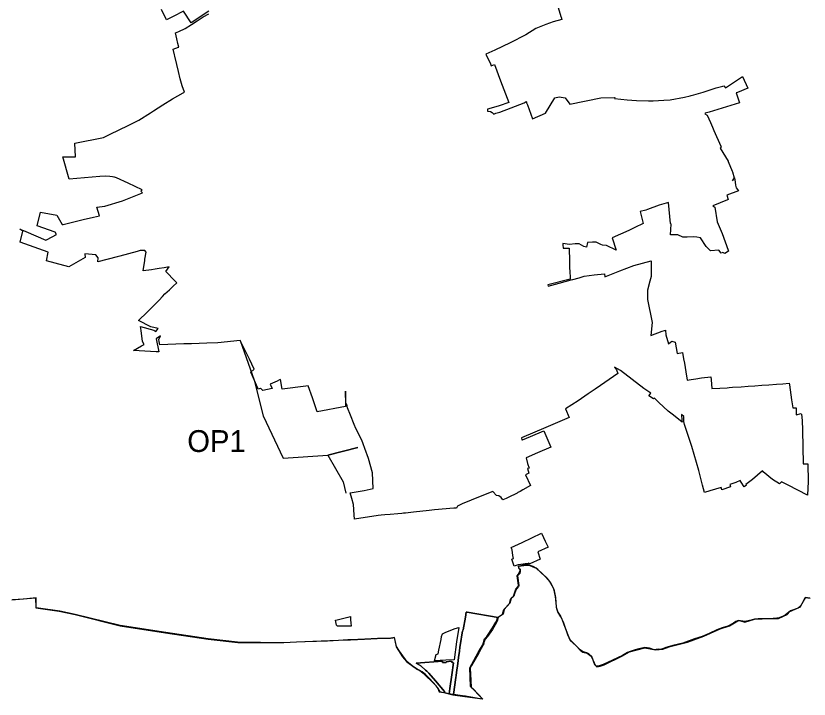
# Model space of a CAD drawing. Extents: x -478490 to -472450, y -1118050 to -1109550.
# Drawn here: x -477155 to -474975, y -1113498 to -1111620 of the extents above; entities that cross this region are included whole.
import ezdxf

# ---------------------------------------------------------------- set-up
doc = ezdxf.new("R2010")
doc.units = 0
for name, color, linetype in [('hranice kú', 7, 'Continuous'), ('Implicitní', 7, 'Continuous'), ('ObPÚ', 7, 'Continuous')]:
    doc.layers.add(name, color=color, linetype=linetype)

msp = doc.modelspace()

# ---------------------------------------------------------------- linework, layer by layer
at = {"layer": 'hranice kú'}
for p, q in [((-475773.3, -1113132.4), (-475752, -1113129.2)), ((-475772.9, -1113137.3), (-475773.3, -1113132.4)), ((-475770, -1113140.3), (-475772.9, -1113137.3)), ((-475752, -1113129.2), (-475745.4, -1113129.5)), ((-475745.4, -1113129.5), (-475736, -1113133)), ((-475736, -1113133), (-475725.4, -1113138.1)), ((-475725.4, -1113138.1), (-475700.6, -1113160.1)), ((-475777.5, -1113158.9), (-475773.1, -1113154.3)), ((-475773.7, -1113184.2), (-475777.5, -1113158.9)), ((-475773.1, -1113154.3), (-475768.7, -1113144)), ((-475768.7, -1113144), (-475770, -1113140.3)), ((-475700.6, -1113160.1), (-475690.7, -1113170.6)), ((-475690.7, -1113170.6), (-475685.4, -1113178)), ((-475685.4, -1113178), (-475676.7, -1113195.1)), ((-475787.5, -1113214.7), (-475780.7, -1113195.1)), ((-475780.7, -1113195.1), (-475774.1, -1113188)), ((-475774.1, -1113188), (-475773.7, -1113184.2)), ((-475676.7, -1113195.1), (-475671.9, -1113217.9)), ((-477165.8, -1113224.6), (-477134.7, -1113222.1)), ((-477134.7, -1113222.1), (-477100.4, -1113219)), ((-477100.4, -1113219), (-477099.3, -1113246.8)), ((-475798.5, -1113234.6), (-475794.6, -1113221.1)), ((-475794.6, -1113221.1), (-475787.5, -1113214.7)), ((-475671.9, -1113217.9), (-475669.7, -1113244.5)), ((-474998.9, -1113244.1), (-474985.7, -1113218)), ((-474985.7, -1113218), (-474972, -1113220.4)), ((-477099.3, -1113246.8), (-477035.2, -1113255.8)), ((-475814.3, -1113251.4), (-475798.5, -1113234.6)), ((-475669.7, -1113244.5), (-475665.3, -1113258.5)), ((-475027.8, -1113257.1), (-474998.9, -1113244.1)), ((-477035.2, -1113255.8), (-476991.4, -1113264.9)), ((-476991.4, -1113264.9), (-476867.7, -1113295.9)), ((-475831.5, -1113273.2), (-475817.6, -1113264.1)), ((-475817.6, -1113264.1), (-475814.3, -1113251.4)), ((-475665.3, -1113258.5), (-475658.2, -1113269.2)), ((-475658.2, -1113269.2), (-475650.2, -1113288)), ((-475059, -1113276.2), (-475035.7, -1113264.8)), ((-475035.7, -1113264.8), (-475027.8, -1113257.1)), ((-475844.9, -1113301.8), (-475835.7, -1113286.1)), ((-475835.7, -1113286.1), (-475833, -1113280.7)), ((-475833, -1113280.7), (-475831.5, -1113273.2)), ((-475650.2, -1113288), (-475638.7, -1113319.8)), ((-475193.7, -1113296.3), (-475171.4, -1113282.5)), ((-475171.4, -1113282.5), (-475166.6, -1113281.7)), ((-475166.6, -1113281.7), (-475151.7, -1113286)), ((-475151.7, -1113286), (-475125.2, -1113277.7)), ((-475125.2, -1113277.7), (-475104.3, -1113277.2)), ((-475104.3, -1113277.2), (-475059, -1113276.2)), ((-476867.7, -1113295.9), (-476743.2, -1113315.4)), ((-475860.6, -1113325.1), (-475844.9, -1113301.8)), ((-475264.7, -1113324.8), (-475219.6, -1113304.2)), ((-475219.6, -1113304.2), (-475193.7, -1113296.3)), ((-476743.2, -1113315.4), (-476626.6, -1113332.5)), ((-476626.6, -1113332.5), (-476544.9, -1113342)), ((-476161.9, -1113331.2), (-476125.1, -1113329.7)), ((-476125.1, -1113329.7), (-476118.9, -1113328.8)), ((-476118.9, -1113328.8), (-476114.9, -1113328.2)), ((-476114.9, -1113328.2), (-476109.7, -1113353.1)), ((-475871.5, -1113348.3), (-475867, -1113332.2)), ((-475867, -1113332.2), (-475860.6, -1113325.1)), ((-475638.7, -1113319.8), (-475631.3, -1113336.1)), ((-475309.3, -1113340.8), (-475264.7, -1113324.8)), ((-476544.9, -1113342), (-476419.1, -1113342)), ((-476419.1, -1113342), (-476383.4, -1113340.4)), ((-476383.4, -1113340.4), (-476335, -1113338.6)), ((-476109.7, -1113353.1), (-476101, -1113365.5)), ((-475878.1, -1113358.5), (-475871.5, -1113348.3)), ((-475631.3, -1113336.1), (-475615.2, -1113350.7)), ((-475615.2, -1113350.7), (-475604.2, -1113363.4)), ((-475468.7, -1113368), (-475426.9, -1113356.4)), ((-475426.9, -1113356.4), (-475397.4, -1113362.5)), ((-475376.6, -1113360.5), (-475357.1, -1113353.3)), ((-475357.1, -1113353.3), (-475309.3, -1113340.8)), ((-476101, -1113365.5), (-476080.1, -1113395.4)), ((-475907.7, -1113411.9), (-475884.7, -1113369.8)), ((-475884.7, -1113369.8), (-475878.1, -1113358.5)), ((-475604.2, -1113363.4), (-475596.5, -1113368.1)), ((-475596.5, -1113368.1), (-475585.2, -1113371.1)), ((-475585.2, -1113371.1), (-475573.8, -1113379.5)), ((-475489.2, -1113379.7), (-475468.7, -1113368)), ((-475397.4, -1113362.5), (-475376.6, -1113360.5)), ((-476080.1, -1113395.4), (-476057.9, -1113411.9)), ((-475573.8, -1113379.5), (-475565.7, -1113398.2)), ((-475565.7, -1113398.2), (-475562.9, -1113404.6)), ((-475538.1, -1113403.7), (-475489.2, -1113379.7)), ((-476057.9, -1113411.9), (-476054.4, -1113413.8)), ((-476054.4, -1113413.8), (-476051.1, -1113415.7)), ((-476051.1, -1113415.7), (-476048.5, -1113417)), ((-476048.5, -1113417), (-476046.4, -1113418.3)), ((-476046.4, -1113418.3), (-476043.5, -1113419.9)), ((-476043.5, -1113419.9), (-476040.8, -1113421.3)), ((-476040.8, -1113421.3), (-476035.4, -1113426.1)), ((-475905.2, -1113463.1), (-475907.7, -1113411.9)), ((-475562.9, -1113404.6), (-475558.3, -1113408.5)), ((-475558.3, -1113408.5), (-475549.6, -1113407.3)), ((-475549.6, -1113407.3), (-475538.1, -1113403.7)), ((-476035.4, -1113426.1), (-476004.1, -1113456)), ((-476004.1, -1113456), (-475996, -1113465.9)), ((-475872.8, -1113496.5), (-475905.2, -1113463.1)), ((-475996, -1113465.9), (-475991.2, -1113477.6)), ((-475991.2, -1113477.6), (-475978.7, -1113479.6)), ((-475978.7, -1113479.6), (-475953.9, -1113485.4)), ((-475953.9, -1113485.4), (-475920.8, -1113490)), ((-475920.8, -1113490), (-475872.8, -1113496.5))]:
    msp.add_line(p, q, dxfattribs=at)
msp.add_lwpolyline([(-476335, -1113338.6), (-476331.3, -1113338.5), (-476328.9, -1113338.5), (-476309.5, -1113337.6), (-476304, -1113337.5), (-476297.9, -1113337.3), (-476282.7, -1113336.7), (-476267.7, -1113335.9), (-476235.2, -1113334.5), (-476196.6, -1113332.7), (-476161.9, -1113331.2)], dxfattribs=at)
at = {"layer": 'Implicitní'}
msp.add_lwpolyline([(-476537.9, -1112512.5), (-476499.6, -1112620.8), (-476475.1, -1112719.5), (-476420.2, -1112835.8), (-476297.4, -1112827.1), (-476215, -1112805.8), (-476297.4, -1112827.1), (-476255.6, -1112900.3), (-476255.6, -1112900.3), (-476247.5, -1112931.7)], dxfattribs=at)
at = {"layer": 'ObPÚ'}
for p, q in [((-475744.6, -1113124.7), (-475747, -1113124)), ((-475742.5, -1113125.3), (-475744.6, -1113124.7))]:
    msp.add_line(p, q, dxfattribs=at)
for points in [[(-475667.3, -1111587.5), (-475657.2, -1111621.4), (-475656.6, -1111623.4), (-475654.6, -1111630.4), (-475677.9, -1111636.7), (-475698.4, -1111643.4), (-475726.3, -1111654.9), (-475753.2, -1111671.8), (-475796.4, -1111694.5), (-475838.6, -1111714.6), (-475863.6, -1111725.3), (-475850.8, -1111752.1), (-475848.8, -1111757.6), (-475839.8, -1111754), (-475822.7, -1111798.9), (-475799.8, -1111858.4), (-475826.7, -1111867.4), (-475849.1, -1111873.9), (-475859, -1111876.8), (-475858.5, -1111881.8), (-475850.5, -1111882.4), (-475846, -1111885.5), (-475841.5, -1111890.5), (-475835.8, -1111887.6), (-475824.7, -1111884.4), (-475793.6, -1111873.2), (-475757.8, -1111858.6), (-475752.6, -1111855.2), (-475751.9, -1111856.2), (-475751.3, -1111858.9), (-475749.1, -1111864.3), (-475735.2, -1111903), (-475699, -1111887), (-475673.7, -1111845.3), (-475661.5, -1111842.2), (-475645.4, -1111845.7), (-475632.5, -1111862.8), (-475547.6, -1111845), (-475509.3, -1111844.8), (-475509.4, -1111846.9), (-475475.1, -1111850.7), (-475449.8, -1111852.2), (-475416.4, -1111853.9), (-475403.4, -1111853.3), (-475374.7, -1111851.3), (-475356.5, -1111850.4), (-475317.7, -1111843.9), (-475302.2, -1111839.9), (-475298.9, -1111839.2), (-475291.5, -1111836.7), (-475266.1, -1111830), (-475230.2, -1111817.8), (-475212.6, -1111813.1), (-475209, -1111812.4), (-475205, -1111817.9), (-475157.9, -1111786.7), (-475143.1, -1111818.7), (-475171.7, -1111830.3), (-475175.1, -1111831.6), (-475166.6, -1111858.8), (-475250, -1111885.1), (-475260.4, -1111887.5), (-475261.4, -1111889.2), (-475254.8, -1111892.9), (-475246.3, -1111913), (-475243.5, -1111919.3), (-475240.6, -1111926), (-475236.6, -1111935), (-475217.4, -1111978.1), (-475216.4, -1111980.6), (-475219.2, -1111983.5), (-475197.7, -1112019.3), (-475197.5, -1112020.1), (-475186.2, -1112046.7), (-475185.4, -1112048.9), (-475181.2, -1112065.4), (-475185.4, -1112073.3), (-475179.8, -1112065.2), (-475178.2, -1112076.8), (-475177.1, -1112085), (-475175.1, -1112092.7)], [(-476624, -1111606.8), (-476672.6, -1111638.9), (-476693.6, -1111607.2), (-476722.7, -1111621.8), (-476740.9, -1111630.8), (-476754.6, -1111602.9)], [(-476716.8, -1112349.4), (-476742.1, -1112322.2), (-476733.5, -1112310), (-476747.3, -1112312.3), (-476761, -1112314.4), (-476772.2, -1112316.4), (-476782.1, -1112317.8), (-476805.1, -1112321.1), (-476800.4, -1112292.3), (-476799.8, -1112288.9), (-476796.8, -1112269.7), (-476799.8, -1112265.1), (-476813.2, -1112264.9), (-476821.5, -1112267.2), (-476869, -1112280.1), (-476875.9, -1112282), (-476929.6, -1112295.7), (-476928.6, -1112284.7), (-476935.1, -1112277.1), (-476965.2, -1112273.8), (-476964.1, -1112283.8), (-477009.1, -1112309.9), (-477046.3, -1112299.5), (-477070.7, -1112293.1), (-477066, -1112269.4), (-477142.6, -1112241.9), (-477135.3, -1112211.7), (-477143.2, -1112206.4), (-477133.2, -1112209.5), (-477127, -1112212.2), (-477072, -1112236.3), (-477068.2, -1112234.2), (-477043, -1112220.5), (-477046.2, -1112214.4), (-477096.2, -1112196.9), (-477087, -1112159.4), (-477041.6, -1112167.7), (-477027.1, -1112193.6), (-477024.7, -1112193), (-476969.7, -1112179.8), (-476941.5, -1112173.1), (-476924.9, -1112169.2), (-476932, -1112146), (-476910.3, -1112142.8), (-476862, -1112127.9), (-476806.8, -1112106.1), (-476811.6, -1112102), (-476807.6, -1112098), (-476845.7, -1112080.1), (-476878, -1112065), (-476883.2, -1112063.6), (-476885.7, -1112063.1), (-476889.1, -1112062.6), (-476896.8, -1112061.7), (-476908.9, -1112060.2), (-476924.1, -1112061.6), (-477007.9, -1112069), (-477025.9, -1112007.4), (-476990.5, -1112007), (-476992.4, -1111969.7), (-476913.9, -1111954.4), (-476895, -1111945), (-476846.1, -1111921.6), (-476816.5, -1111906.9), (-476785, -1111886.7), (-476776.6, -1111881.3), (-476750.7, -1111864.8), (-476724.3, -1111848.2), (-476695, -1111831.9), (-476691.4, -1111829.9), (-476697.9, -1111811.9), (-476703.4, -1111792.7), (-476707.7, -1111773.2), (-476712.7, -1111753.4), (-476717.9, -1111731.2), (-476718.9, -1111726.7), (-476722.5, -1111711.7), (-476708, -1111706.3), (-476706.6, -1111705.8), (-476709.3, -1111696.3), (-476712.4, -1111683.4), (-476716.3, -1111667), (-476706.5, -1111662.8), (-476689.2, -1111655), (-476672.4, -1111644.1), (-476656.2, -1111633.3), (-476639.8, -1111622.5), (-476624.6, -1111614.3)], [(-475175.1, -1112092.7), (-475169.4, -1112100.7), (-475201.2, -1112112.9), (-475197.7, -1112124.4), (-475199.7, -1112125.2), (-475239.7, -1112142.5), (-475233.8, -1112145.8), (-475227.7, -1112185.9), (-475214.4, -1112218.3), (-475197.3, -1112264.1), (-475196.2, -1112266.6), (-475206.7, -1112272.6), (-475211.8, -1112270.3), (-475216.6, -1112272.3), (-475223.2, -1112264.3), (-475246.3, -1112265.9), (-475258.3, -1112254.1), (-475273.6, -1112230.2), (-475283.6, -1112228.6), (-475293.4, -1112227.1), (-475310, -1112228.3), (-475321.7, -1112228), (-475335.4, -1112221.9), (-475355.5, -1112221.9), (-475353.9, -1112192.4), (-475355.8, -1112190.7), (-475361.4, -1112132.7), (-475386.9, -1112139.9), (-475419.2, -1112152.4), (-475423.8, -1112153.6), (-475439, -1112157.5), (-475430.9, -1112190.6), (-475453.5, -1112201.6), (-475470.5, -1112209.5), (-475516.3, -1112229.6), (-475504.9, -1112263.8), (-475531.9, -1112251.3), (-475542.4, -1112249.8), (-475547.1, -1112248.7), (-475559.9, -1112241.8), (-475569.8, -1112242.1), (-475583.6, -1112242.6), (-475586.4, -1112255.5), (-475593.7, -1112253.8), (-475606.8, -1112246.9), (-475618.2, -1112246.2), (-475633.8, -1112248.7), (-475652, -1112245.7), (-475652.2, -1112249.6), (-475650.9, -1112258.7), (-475634, -1112258.7), (-475633.3, -1112294.1), (-475633, -1112316.4), (-475632.9, -1112317.5), (-475631.8, -1112343.6), (-475693.2, -1112358.8), (-475692.2, -1112362.7), (-475661.8, -1112354.6), (-475628.7, -1112345.5), (-475623.9, -1112344.2), (-475607, -1112340), (-475592.9, -1112335.1), (-475565.4, -1112331.9), (-475537.3, -1112329.1), (-475536.7, -1112337.2), (-475494.7, -1112320.7), (-475456.5, -1112305.8), (-475409.4, -1112293.6), (-475409.3, -1112335.9), (-475412.3, -1112349), (-475419.4, -1112373.5), (-475419, -1112399.7), (-475406.5, -1112462.9), (-475410.2, -1112498.6), (-475379.2, -1112486.8), (-475372.2, -1112484.3), (-475370, -1112483.5), (-475368.5, -1112496.7), (-475361.8, -1112521.1), (-475351.9, -1112514.1), (-475343.5, -1112516.4), (-475337.6, -1112547.5), (-475322.6, -1112544.6), (-475319.8, -1112562.9), (-475317.8, -1112574.1), (-475313.4, -1112597.9), (-475310.2, -1112621.1), (-475299.6, -1112619.4), (-475286, -1112617.2), (-475271, -1112614.7), (-475244.9, -1112612.1), (-475244.2, -1112620), (-475242.4, -1112644.2), (-475220.3, -1112643.3), (-475200.7, -1112641.8), (-475194.4, -1112641.2)], [(-475821.3, -1112943.2), (-475827.5, -1112939.1), (-475834.2, -1112937.6), (-475844.4, -1112927.1), (-475878.8, -1112941), (-475928, -1112960.8), (-475929.8, -1112961.5), (-475941.2, -1112967.3), (-475944, -1112972.5), (-475951.3, -1112972.4), (-476004.5, -1112977.3), (-476018.9, -1112979.2), (-476061.7, -1112984), (-476084.3, -1112986.2), (-476089.5, -1112986.6), (-476094, -1112987), (-476104.8, -1112988), (-476125.8, -1112990), (-476140.4, -1112990.8), (-476151, -1112991.9), (-476159.5, -1112992.8), (-476224.1, -1113003.1), (-476225.4, -1112991.1), (-476226.7, -1112962.3), (-476231.3, -1112946.2), (-476236.3, -1112930.9), (-476197.9, -1112923.9), (-476173.1, -1112918.5), (-476175.1, -1112875.5), (-476185.9, -1112836.7), (-476189.6, -1112826.3), (-476192, -1112818.9), (-476203.9, -1112785.9), (-476220.3, -1112754.1), (-476224.8, -1112742.7), (-476235.1, -1112717.1), (-476243.4, -1112697.3), (-476244.9, -1112686.6), (-476247.7, -1112687.1), (-476248.8, -1112651.6), (-476249, -1112693.6), (-476326.6, -1112708.5), (-476339.7, -1112669.9), (-476351, -1112636.6), (-476357.4, -1112637.7), (-476422.9, -1112645.9), (-476427.4, -1112619.4), (-476430.3, -1112620.4), (-476436.9, -1112623.5), (-476455.7, -1112631.7), (-476450.1, -1112644), (-476476, -1112649.4), (-476482.1, -1112643.1), (-476483.7, -1112643.8), (-476488.8, -1112645.9), (-476490.1, -1112642.9), (-476509, -1112598.8), (-476499.6, -1112590.5), (-476512.7, -1112563.7), (-476522.7, -1112543.4), (-476532.6, -1112523.3), (-476537.9, -1112512.5), (-476599.3, -1112518.8), (-476629.5, -1112519.4), (-476650.7, -1112520.2), (-476671.7, -1112520.8), (-476692.9, -1112521.6), (-476759.4, -1112524), (-476760.7, -1112514.9), (-476761.7, -1112509.6), (-476757.2, -1112499.1), (-476768.7, -1112507.4), (-476762, -1112543), (-476768.7, -1112542.8), (-476830.9, -1112539.2), (-476809.4, -1112526.4), (-476801.8, -1112522.8), (-476806.4, -1112514.5), (-476810.3, -1112484.8), (-476811.8, -1112473.6), (-476775.7, -1112483.8), (-476770.1, -1112487.8), (-476764, -1112478.9), (-476783.5, -1112474.4), (-476817.6, -1112456.8), (-476793.5, -1112434), (-476780, -1112420.5), (-476777, -1112417.7), (-476761.2, -1112401.3), (-476751.7, -1112391.3), (-476745.1, -1112384.2), (-476732.8, -1112372.5), (-476722.4, -1112363.2), (-476712.3, -1112353.3), (-476715.3, -1112351), (-476716.8, -1112349.4)], [(-475194.4, -1112641.2), (-475185.4, -1112640.5), (-475161.7, -1112639.1), (-475142.9, -1112637.6), (-475124, -1112636.4), (-475105, -1112635), (-475085.7, -1112634.1), (-475065.1, -1112632.4), (-475047.4, -1112630.9), (-475030, -1112629.5), (-475029.4, -1112633.9), (-475028.6, -1112633.9), (-475023.8, -1112674.9), (-475019.8, -1112697.4), (-475011, -1112696.8), (-475010.4, -1112709.6), (-475010.4, -1112716.5), (-474996.6, -1112713), (-474996.4, -1112714.1), (-474994.6, -1112731.6), (-474993.4, -1112758.1), (-474991.2, -1112850.8), (-474978.9, -1112851.1), (-474978.1, -1112899.4), (-474979.1, -1112937.4), (-475032.7, -1112909.2), (-475050.7, -1112900.4), (-475056.1, -1112905.6), (-475076, -1112894.2), (-475100.9, -1112872.7), (-475103.2, -1112870.5), (-475130.9, -1112893.6), (-475148.6, -1112907.7), (-475146.9, -1112909.8), (-475153.2, -1112914.5), (-475161.6, -1112901.4), (-475164.2, -1112897), (-475176.8, -1112902.4), (-475190.4, -1112906.6), (-475193, -1112907.4), (-475191.2, -1112914.5), (-475215, -1112922.7), (-475216.2, -1112918.1), (-475216.8, -1112915.6), (-475247.6, -1112925.1), (-475262.7, -1112929.7), (-475267.7, -1112909.4), (-475278.3, -1112869.6), (-475297.5, -1112803.4), (-475317.6, -1112742.9), (-475319.3, -1112735), (-475319.6, -1112720.8), (-475325.4, -1112715.5), (-475324.9, -1112732.2), (-475323.6, -1112736.3), (-475347.7, -1112717), (-475362, -1112705.8), (-475387.6, -1112682.8), (-475400.2, -1112670.4), (-475402.3, -1112672.8), (-475415.1, -1112664), (-475409.9, -1112657), (-475429, -1112644), (-475493.6, -1112594.9), (-475510, -1112585), (-475504.4, -1112592.7), (-475500.2, -1112602.9), (-475548.7, -1112636.1), (-475563.2, -1112645.9), (-475582.4, -1112659), (-475609.9, -1112677.6), (-475644, -1112700.2), (-475634.1, -1112723.5), (-475698.2, -1112750.9), (-475765.5, -1112779.2), (-475764.2, -1112785.3), (-475762.8, -1112784.7), (-475740.8, -1112775.6), (-475704.4, -1112759.9), (-475684.8, -1112805), (-475721.1, -1112820.7), (-475752.9, -1112834.2), (-475749.2, -1112850), (-475744.5, -1112862.5), (-475748.9, -1112864.2), (-475744.9, -1112876.6), (-475754.6, -1112881.6), (-475740.7, -1112910.4), (-475761.5, -1112922.4), (-475769.3, -1112926.9), (-475775.6, -1112930.1), (-475776.9, -1112931.4), (-475801.9, -1112943.8), (-475807.1, -1112946.1), (-475816.2, -1112950.3), (-475821.3, -1112943.2)], [(-475710, -1113041.8), (-475709.1, -1113043.6), (-475700.1, -1113063.1), (-475692.4, -1113080.1), (-475720.3, -1113092.4), (-475713.9, -1113113), (-475742.3, -1113125.9), (-475744.3, -1113125.4), (-475747.1, -1113125.2), (-475755.1, -1113125.3), (-475766.7, -1113127.6), (-475774.9, -1113128.9), (-475785.3, -1113131.9), (-475792, -1113112.6), (-475790.1, -1113112), (-475787.6, -1113111.1), (-475788.9, -1113103), (-475791.1, -1113087.2), (-475791.6, -1113085.8), (-475792.8, -1113082.4), (-475793.3, -1113080.9), (-475763.7, -1113066.8), (-475710, -1113041.8)], [(-475198.5, -1113296.9), (-475213.9, -1113301.5), (-475228.9, -1113307.4), (-475249.6, -1113317.1), (-475268.9, -1113325.3), (-475289.9, -1113332.2), (-475322.2, -1113343.7), (-475349.4, -1113350.5), (-475368.4, -1113355.9), (-475377.8, -1113359.3), (-475383.5, -1113360.7), (-475389.5, -1113360.4), (-475400.9, -1113361.8), (-475413.6, -1113357.9), (-475426.3, -1113355.6), (-475446.3, -1113360.1), (-475455.6, -1113363.4), (-475467.2, -1113366.3), (-475474.1, -1113369.3), (-475488, -1113377.9), (-475515.5, -1113390.5), (-475540.5, -1113402.8), (-475554.8, -1113406.9), (-475558.9, -1113406.6), (-475561.4, -1113405.6), (-475563.8, -1113403.3), (-475572.2, -1113380.4), (-475580.7, -1113372.9), (-475585.9, -1113369.9), (-475595.6, -1113367.1), (-475604.5, -1113362.3), (-475615.8, -1113350), (-475631.3, -1113334.8), (-475635.3, -1113326.5), (-475648.5, -1113293.4), (-475653.1, -1113280.5), (-475657.3, -1113271.2), (-475665.2, -1113257.3), (-475668.2, -1113249.8), (-475669.4, -1113243.4), (-475672.3, -1113215.6), (-475676.7, -1113194.5), (-475681.4, -1113184.9), (-475687.6, -1113173.9), (-475695.2, -1113164.7), (-475720.1, -1113141.3), (-475725.2, -1113137.8), (-475733.2, -1113133.4), (-475747.2, -1113128.6), (-475754.8, -1113128.7), (-475760.6, -1113129.4), (-475770.6, -1113131.7), (-475773.2, -1113131.8), (-475773.5, -1113135), (-475772.5, -1113137.4), (-475769.1, -1113140.7), (-475769.1, -1113142.3), (-475769.2, -1113146.8), (-475770, -1113152.1), (-475772.1, -1113154.5), (-475776.3, -1113158.9), (-475773, -1113185.1), (-475773.4, -1113188.3), (-475779.3, -1113194.7), (-475783.8, -1113205.7), (-475786.5, -1113214.6), (-475794, -1113221.4), (-475797.1, -1113234.2), (-475812.5, -1113251.2), (-475815.7, -1113264.3), (-475829.4, -1113273.5), (-475914.9, -1113258.4), (-475916.9, -1113258.2), (-475919.5, -1113272.1), (-475925.9, -1113307.1), (-475927.6, -1113310.8), (-475929.4, -1113321.1), (-475931.8, -1113338.7), (-475934.6, -1113354.7), (-475936.1, -1113366.1), (-475938.2, -1113382.8), (-475940.3, -1113399.7), (-475943.8, -1113423.9), (-475945, -1113432.9), (-475945.9, -1113437.9), (-475951.7, -1113485.1), (-475955.2, -1113484.4), (-475964.2, -1113482.6), (-475962, -1113468.4), (-475956.7, -1113430.6), (-475952.3, -1113398), (-475954.6, -1113398.1), (-475955, -1113394.8), (-475956.8, -1113395), (-475958.7, -1113395.2), (-475958.8, -1113393.6)], [(-475958.8, -1113393.6), (-475972.4, -1113394.8), (-475972.3, -1113396.4), (-475982.5, -1113397.2), (-475982.8, -1113392.9), (-476055, -1113398.4), (-476042.1, -1113406.1), (-476028.8, -1113417.9), (-476025.5, -1113420.8), (-476019.5, -1113425.8), (-476002, -1113447), (-475977.1, -1113476.9), (-475976.7, -1113480), (-475983.3, -1113479.3), (-475989, -1113477.7), (-475994, -1113468.3), (-475999.4, -1113460.9), (-476018.3, -1113441), (-476029.3, -1113430.2), (-476038, -1113422.8), (-476044.7, -1113418.6), (-476051.6, -1113415.3), (-476061.6, -1113408.9), (-476079.9, -1113394.1), (-476091, -1113380.9), (-476108.8, -1113353.8), (-476114, -1113328.4), (-476124.3, -1113330.1), (-476161, -1113331.2), (-476195.9, -1113333.1), (-476234.3, -1113334.6), (-476239.3, -1113334.9), (-476242.1, -1113335), (-476268.1, -1113336.1), (-476315.8, -1113337.8), (-476383.3, -1113341), (-476418.4, -1113342.7), (-476545.7, -1113341.3), (-476626.5, -1113331.7), (-476742.5, -1113314.7), (-476868.4, -1113295.6), (-476991.4, -1113264.8), (-477034.1, -1113256), (-477098.3, -1113246.9), (-477099.1, -1113218.9), (-477133.3, -1113222.8), (-477164, -1113225.1)], [(-474973.5, -1113220.4), (-474985.4, -1113217.8), (-474998.6, -1113242.1), (-475005.2, -1113247.5), (-475026, -1113254.6), (-475041.2, -1113266.8), (-475046.5, -1113269.7), (-475059.7, -1113275.4), (-475063.6, -1113275.2), (-475074, -1113276.3), (-475114.8, -1113276.6), (-475125.6, -1113277.5), (-475134.1, -1113280.6), (-475152.1, -1113284.6), (-475168.9, -1113281), (-475176.6, -1113284.4), (-475182.5, -1113288.4), (-475198.5, -1113296.9)], [(-475919.5, -1113272.1), (-475916.9, -1113258.2), (-475914.9, -1113258.4), (-475829.4, -1113273.5), (-475831.9, -1113283.6), (-475833.9, -1113286.9), (-475844.8, -1113306.3), (-475858.4, -1113325.5), (-475865.5, -1113332.6), (-475866.6, -1113337), (-475868.6, -1113341.6), (-475870.1, -1113348.5), (-475871.2, -1113349.7), (-475876.2, -1113358.8), (-475882.6, -1113370.2), (-475902.5, -1113404.8), (-475906.8, -1113412.2), (-475905.7, -1113429.1), (-475903.9, -1113464.4), (-475898.5, -1113469.1), (-475871.7, -1113497.5), (-475884.8, -1113495.4), (-475919, -1113489.8), (-475927.3, -1113488.7), (-475951.7, -1113485.1), (-475945.9, -1113437.9), (-475945, -1113432.9), (-475943.8, -1113423.9), (-475940.3, -1113399.7), (-475938.2, -1113382.8), (-475936.1, -1113366.1), (-475934.6, -1113354.7), (-475931.8, -1113338.7), (-475929.4, -1113321.1), (-475927.6, -1113310.8), (-475925.9, -1113307.1), (-475919.5, -1113272.1)], [(-476235, -1113270.3), (-476234.9, -1113272.9), (-476234.7, -1113278.9), (-476234.1, -1113289.1), (-476233, -1113296.2), (-476232.8, -1113297.4), (-476246.2, -1113296.9), (-476271, -1113297.1), (-476274, -1113294.7), (-476276.7, -1113280.9), (-476275, -1113280.4), (-476246.5, -1113273.2), (-476241.6, -1113271.9), (-476235, -1113270.3)], [(-475937.1, -1113300.3), (-475943.5, -1113340.5), (-475950.6, -1113389.2), (-475972.8, -1113390.3), (-476004.6, -1113392.3), (-475999.6, -1113375.3), (-475994.2, -1113373.4), (-475992.2, -1113363.2), (-475986.2, -1113334.1), (-475984.9, -1113325.8), (-475982, -1113318.2), (-475972.8, -1113313.2), (-475947.2, -1113303.8), (-475937.1, -1113300.3)], [(-476055, -1113398.4), (-475982.8, -1113392.9), (-475982.5, -1113397.2), (-475972.3, -1113396.4), (-475972.4, -1113394.8), (-475958.8, -1113393.6), (-475958.7, -1113395.2), (-475956.8, -1113395), (-475955, -1113394.8), (-475954.6, -1113398.1), (-475952.3, -1113398), (-475956.7, -1113430.6), (-475962, -1113468.4), (-475964.2, -1113482.6), (-475976.7, -1113480), (-475977.1, -1113476.9), (-476002, -1113447), (-476019.5, -1113425.8), (-476025.5, -1113420.8), (-476028.8, -1113417.9), (-476042.1, -1113406.1), (-476055, -1113398.4)]]:
    msp.add_lwpolyline(points, dxfattribs=at)

# ---------------------------------------------------------------- texts
at = {"layer": 'Implicitní'}
msp.add_text('OP1', height=60, dxfattribs=at).set_placement((-476683.6, -1112818.4))

doc.saveas('drawing.dxf')
